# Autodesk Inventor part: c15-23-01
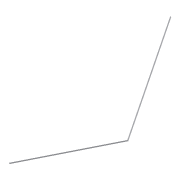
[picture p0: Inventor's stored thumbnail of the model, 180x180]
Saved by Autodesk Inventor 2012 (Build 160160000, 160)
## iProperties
Created: 2011-02
Part Number: c15-23-01
Material: Default
Document SubType Name: Modeling
Designer: Beta-8540w
Density: 1 g/cm^3
Author: Beta-8540w
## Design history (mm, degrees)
derived "c15-15.ipt" dims "d3" = 0, "drawer_depth" = 508, "bottom_width" = 552.45, "bottom_thickness" = 6.35
body "Solid1"
feature "Solid1::c15-15.ipt" dims "d3" = 0, "drawer_depth" = 508, "bottom_width" = 552.45, "bottom_thickness" = 6.35, "ScaleForDerivedMember" = 10
tag "TaggingFeature1"
